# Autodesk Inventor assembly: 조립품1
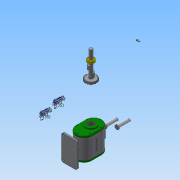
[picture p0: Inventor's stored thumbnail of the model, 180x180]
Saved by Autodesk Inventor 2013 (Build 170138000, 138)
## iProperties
Created: 2018-10
Part Number: 조립품1
Document SubType Name: Assembly
Designer: Administrator
Author: Administrator
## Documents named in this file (15)
- C:\Users\Administrator\Desktop\381007V1032\조립품1.iam
- C:\Users\Administrator\Desktop\381007V1032\본체.ipt
- C:\Users\Administrator\Desktop\381007V1032\가변스프링1.ipt
- C:\Users\Administrator\Desktop\381007V1032\가변스프링2.ipt
- C:\Users\Administrator\Desktop\381007V1032\뒤커버.ipt
- C:\Users\Administrator\Desktop\381007V1032\메인축.ipt
- C:\Users\Administrator\Desktop\381007V1032\베어링 608.ipt
- C:\Users\Administrator\Desktop\381007V1032\베어링 6003.ipt
- C:\Users\Administrator\Desktop\381007V1032\볼트 M4.ipt
- C:\Users\Administrator\Desktop\381007V1032\부시.ipt
- C:\Users\Administrator\Desktop\381007V1032\서브축.ipt
- C:\Users\Administrator\Desktop\381007V1032\슬라이더.ipt
- C:\Users\Administrator\Desktop\381007V1032\앞커버.ipt
- C:\Users\Administrator\Desktop\381007V1032\오일실 8 22 7.ipt
- C:\Users\Administrator\Desktop\381007V1032\오일실 17 32 8.ipt
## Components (2 placed, 2 different names)
1. 가변스프링1:1
2. 가변스프링2:1
